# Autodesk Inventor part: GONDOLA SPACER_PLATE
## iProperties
Shininess: 64.0
Length Units: 11272
Angle Units: 11279
Time Units: 11290
Mass Units: 11286
Length Display Precision: 3
Angle Display Precision: 2
Compacted: True
Part Number: GONDOLA SPACER_PLATE
Document SubType Name: Modeling
Created: 2004-08
Designer: John Blackburn
Manufacturer: Standard
Standards Organization: Custom
Material: PVC-Piping
Density: 0.0
Volumn: 0.0
Area: 0.0
PropertySet Name: Model Information
Control State: 0
Master: False
Checked Out: False
Author: John Blackburn
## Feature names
1. ExtrusionBlind1
2. AM_HOLE_SI0029_1 [Hole]
3. AM_HOLE_SI0029_2 [Hole]
4. AM_HOLE_SI0029_3 [Hole]
5. AM_HOLE_SI0029_4 [Hole]
6. AM_HOLE_0301DE_1 [Hole]
7. AM_HOLE_0301DE_2 [Hole]
